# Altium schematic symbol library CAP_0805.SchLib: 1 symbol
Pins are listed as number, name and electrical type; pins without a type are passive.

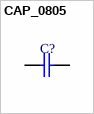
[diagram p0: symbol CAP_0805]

## CAP_0805
designator C?
footprint CAP_0805 (Ceramic chip capacitor)
pins: 1, 2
